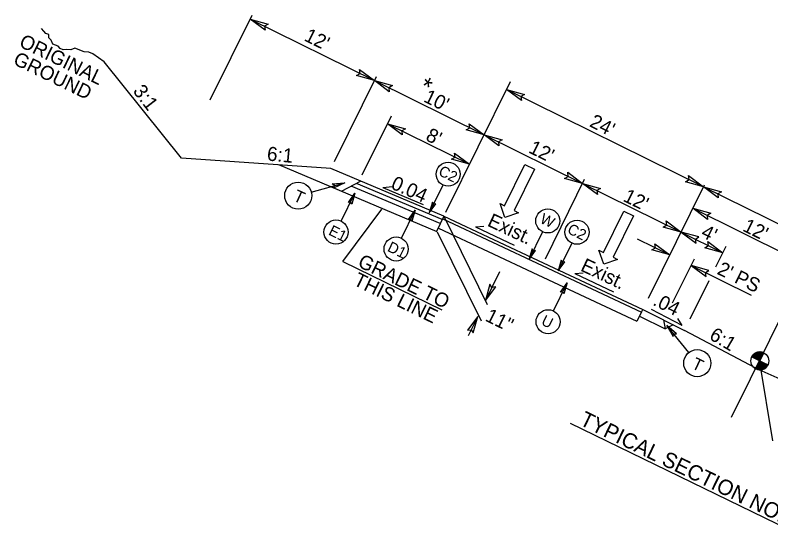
# Model space of a CAD drawing. Extents: x 1518247 to 1523638, y 635234 to 639927.
# Drawn here: x 1518468 to 1519070, y 637598 to 638013 of the extents above; entities that cross this region are included whole.
import ezdxf

# ---------------------------------------------------------------- set-up
doc = ezdxf.new("R2010")
doc.units = 0
for name, color, linetype in [('DTM TIN Hull White', 7, 'Continuous'), ('Prop Dimension', 7, 'Continuous'), ('Prop Dimension Text', 7, 'Continuous'), ('Prop Lane Arrow CELL', 7, 'Continuous'), ('Prop Shade Light', 7, 'Continuous'), ('Typical Grade Point Symbol CELL', 7, 'Continuous'), ('Typical Hinge Slope Interstate CELL', 7, 'Continuous'), ('Typical ID Circle CELL', 7, 'Continuous'), ('Typical Pavement Slope CELL', 7, 'Continuous'), ('Typical Pavement Slope Information CELL', 7, 'Continuous'), ('Typical Text Centerline CELL', 7, 'Continuous'), ('Typical Text General CELL', 7, 'Continuous'), ('Typical Text ID Circle CELL', 7, 'Continuous'), ('Typical Text Label CELL', 7, 'Continuous')]:
    doc.layers.add(name, color=color, linetype=linetype)

# ---------------------------------------------------------------- blocks, each defined once
blk = doc.blocks.new('TERMINATOR')
at = {"layer": 'Prop Shade Light'}
blk.add_lwpolyline([(-0.469, 0.081), (0, 0), (-0.471, -0.083), (-0.411, 0)], close=True, dxfattribs=at)

msp = doc.modelspace()

# ---------------------------------------------------------------- linework, layer by layer
at = {"layer": 'DTM TIN Hull White'}
for p, q in [((1518808.44, 637851.16), (1518887.66, 637813.98)), ((1518805, 637843.84), (1518884.23, 637806.66)), ((1518887.66, 637813.98), (1518966.8, 637776.83)), ((1518884.23, 637806.66), (1518963.07, 637769.66)), ((1518966.8, 637776.83), (1518963.07, 637769.66))]:
    msp.add_line(p, q, dxfattribs=at)
at = {"layer": 'Prop Dimension'}
for p, q in [((1518623.33, 637945.84), (1518656.73, 638013.45)), ((1518655.11, 638010.18), (1518754.1, 637961.28)), ((1518722.32, 637896.94), (1518755.71, 637964.55)), ((1518754.1, 637961.28), (1518841.47, 637918.12)), ((1518811.03, 637856.5), (1518862.46, 637960.62)), ((1519016.2, 637876.74), (1518859.31, 637954.24)), ((1518744.29, 637886.09), (1518767.58, 637933.23)), ((1518764.45, 637926.91), (1518829.78, 637894.64)), ((1518841.47, 637918.12), (1518919.91, 637879.37)), ((1518890.25, 637819.32), (1518921.53, 637882.64)), ((1518890.25, 637819.32), (1518921.53, 637882.64)), ((1518919.91, 637879.37), (1518998.36, 637840.62)), ((1518972.36, 637787.99), (1519016.9, 637878.16)), ((1519016.2, 637876.74), (1519107.11, 637831.83)), ((1518728.88, 637817.04), (1518760.04, 637858.8)), ((1519007.7, 637859.53), (1519098.61, 637814.63)), ((1518809.41, 637853.23), (1518844, 637782.95)), ((1518804.17, 637840.81), (1518839.01, 637770.02)), ((1518998.36, 637840.62), (1519031.62, 637824.19)), ((1518963.47, 637835.2), (1518989.36, 637822.41)), ((1519026.02, 637812.85), (1519034.23, 637829.47)), ((1518728.88, 637817.04), (1518807.71, 637778.68)), ((1518991.64, 637784.2), (1519008.94, 637819.22)), ((1519006.36, 637814.01), (1519054.28, 637790.34)), ((1518853.65, 637808.9), (1518842.51, 637785.99)), ((1519005.62, 637771.56), (1519020.67, 637802.03)), ((1518836.37, 637773.4), (1518828.87, 637757.98)), ((1519071.38, 637674.28), (1519061.24, 637736.88))]:
    msp.add_line(p, q, dxfattribs=at)
at = {"layer": 'Prop Lane Arrow CELL'}
for p, q in [((1518857.67, 637861.55), (1518873.95, 637894.51)), ((1518873.95, 637894.51), (1518881.72, 637890.67)), ((1518881.72, 637890.67), (1518865.44, 637857.71)), ((1518858.01, 637852.16), (1518854.14, 637863.3)), ((1518854.14, 637863.3), (1518857.67, 637861.55)), ((1518868.97, 637855.97), (1518858.01, 637852.16)), ((1518865.44, 637857.71), (1518868.97, 637855.97)), ((1518936.5, 637824.43), (1518952.78, 637857.39)), ((1518952.78, 637857.39), (1518960.55, 637853.55)), ((1518960.55, 637853.55), (1518944.27, 637820.6)), ((1518936.84, 637815.04), (1518932.97, 637826.18)), ((1518932.97, 637826.18), (1518936.5, 637824.43)), ((1518944.27, 637820.6), (1518947.8, 637818.85)), ((1518947.8, 637818.85), (1518936.84, 637815.04))]:
    msp.add_line(p, q, dxfattribs=at)
at = {"layer": 'Prop Shade Light'}
for points in [[(1518720.52, 637878.94), (1518730.6, 637879.94), (1518721.4, 637875.56), (1518722.15, 637877.61)], [(1518733.29, 637864.21), (1518738.57, 637871.51), (1518736.06, 637862.8), (1518735.14, 637864.51)], [(1518800.24, 637864.48), (1518797.72, 637855.83), (1518803.05, 637863.16), (1518801.14, 637862.84)], [(1518781.18, 637850.68), (1518786.46, 637857.97), (1518783.95, 637849.26), (1518783.03, 637850.98)], [(1518879.62, 637827.25), (1518877.1, 637818.61), (1518882.43, 637825.93), (1518880.52, 637825.61)], [(1518902.92, 637818.27), (1518900.39, 637809.62), (1518905.73, 637816.95), (1518903.81, 637816.63)], [(1518902.29, 637792.76), (1518907.57, 637800.06), (1518905.06, 637791.35), (1518904.14, 637793.06)], [(1518994.65, 637759.6), (1518987.06, 637766.31), (1518991.96, 637757.37), (1518992.55, 637759.47)]]:
    msp.add_lwpolyline(points, close=True, dxfattribs=at)
at = {"layer": 'Typical Grade Point Symbol CELL'}
for p, q in [((1519064.23, 637744.34), (1519061.08, 637737.93)), ((1519054.68, 637741.09), (1519061.08, 637737.93)), ((1519061.08, 637737.93), (1519054.68, 637741.09)), ((1519057.94, 637731.52), (1519061.08, 637737.93)), ((1519061.08, 637737.93), (1519067.5, 637734.79))]:
    msp.add_line(p, q, dxfattribs=at)
for points in [[(1519061.26, 637738.29), (1519054.86, 637741.42)], [(1519061.32, 637738.41), (1519054.92, 637741.55)], [(1519061.38, 637738.54), (1519055, 637741.67)], [(1519061.45, 637738.67), (1519055.08, 637741.79)], [(1519061.51, 637738.8), (1519055.16, 637741.91)], [(1519061.57, 637738.93), (1519055.25, 637742.03)], [(1519061.64, 637739.06), (1519055.33, 637742.15)], [(1519061.7, 637739.18), (1519055.42, 637742.26)], [(1519061.76, 637739.31), (1519055.51, 637742.38)], [(1519061.82, 637739.44), (1519055.6, 637742.49)], [(1519061.89, 637739.57), (1519055.69, 637742.6)], [(1519061.95, 637739.7), (1519055.8, 637742.71)], [(1519062.01, 637739.82), (1519055.89, 637742.83)], [(1519062.08, 637739.95), (1519055.99, 637742.93)], [(1519062.14, 637740.08), (1519056.1, 637743.04)], [(1519062.2, 637740.21), (1519056.2, 637743.15)], [(1519062.26, 637740.34), (1519056.32, 637743.25)], [(1519062.33, 637740.47), (1519056.44, 637743.35)], [(1519062.39, 637740.59), (1519056.56, 637743.45)], [(1519062.45, 637740.72), (1519056.68, 637743.55)], [(1519062.52, 637740.85), (1519056.8, 637743.65)], [(1519062.58, 637740.98), (1519056.94, 637743.74)], [(1519062.64, 637741.11), (1519057.07, 637743.84)], [(1519062.7, 637741.23), (1519057.21, 637743.93)], [(1519062.77, 637741.36), (1519057.35, 637744.02)], [(1519062.83, 637741.49), (1519057.5, 637744.1)], [(1519062.89, 637741.62), (1519057.65, 637744.19)], [(1519062.95, 637741.75), (1519057.8, 637744.27)], [(1519063.02, 637741.88), (1519057.96, 637744.35)], [(1519063.08, 637742), (1519058.12, 637744.43)], [(1519063.14, 637742.13), (1519058.3, 637744.51)], [(1519063.21, 637742.26), (1519058.48, 637744.58)], [(1519063.27, 637742.39), (1519058.65, 637744.65)], [(1519063.33, 637742.52), (1519058.84, 637744.72)], [(1519063.39, 637742.65), (1519059.05, 637744.77)], [(1519063.46, 637742.77), (1519059.26, 637744.83)], [(1519063.52, 637742.9), (1519059.47, 637744.88)], [(1519063.58, 637743.03), (1519059.69, 637744.93)], [(1519063.65, 637743.16), (1519059.93, 637744.98)], [(1519063.71, 637743.29), (1519060.18, 637745.02)], [(1519063.77, 637743.41), (1519060.44, 637745.05)], [(1519063.83, 637743.54), (1519060.73, 637745.06)], [(1519063.9, 637743.67), (1519061.03, 637745.07)], [(1519063.96, 637743.8), (1519061.37, 637745.07)], [(1519064.02, 637743.93), (1519061.73, 637745.05)], [(1519064.09, 637744.06), (1519062.18, 637744.99)], [(1519064.15, 637744.18), (1519062.7, 637744.9)], [(1519064.21, 637744.31), (1519063.51, 637744.65)], [(1519061.13, 637738.03), (1519054.72, 637741.17), (1519054.72, 637741.17)], [(1519061.2, 637738.16), (1519054.79, 637741.3)], [(1519065.76, 637732.55), (1519059.86, 637735.44)], [(1519065.88, 637732.65), (1519059.93, 637735.56)], [(1519066, 637732.75), (1519059.99, 637735.69)], [(1519066.11, 637732.85), (1519060.05, 637735.82)], [(1519066.21, 637732.96), (1519060.11, 637735.95)], [(1519066.32, 637733.07), (1519060.18, 637736.08)], [(1519066.41, 637733.18), (1519060.24, 637736.21)], [(1519066.51, 637733.29), (1519060.3, 637736.33)], [(1519066.61, 637733.4), (1519060.37, 637736.46)], [(1519066.7, 637733.52), (1519060.43, 637736.59)], [(1519066.79, 637733.63), (1519060.49, 637736.72)], [(1519066.88, 637733.75), (1519060.55, 637736.85)], [(1519066.96, 637733.87), (1519060.62, 637736.98)], [(1519067.03, 637733.99), (1519060.68, 637737.1)], [(1519067.11, 637734.11), (1519060.74, 637737.23)], [(1519067.19, 637734.23), (1519060.81, 637737.36)], [(1519067.26, 637734.35), (1519060.87, 637737.49)], [(1519067.33, 637734.48), (1519060.93, 637737.62)], [(1519067.4, 637734.6), (1519060.99, 637737.74)], [(1519067.47, 637734.73), (1519067.47, 637734.73), (1519061.06, 637737.87)], [(1519058.89, 637731.14), (1519057.98, 637731.59)], [(1519059.61, 637730.95), (1519058.04, 637731.72)], [(1519060.11, 637730.86), (1519058.1, 637731.85)], [(1519060.53, 637730.82), (1519058.17, 637731.97)], [(1519060.89, 637730.8), (1519058.23, 637732.1)], [(1519061.23, 637730.79), (1519058.29, 637732.23)], [(1519061.52, 637730.81), (1519058.36, 637732.36)], [(1519061.79, 637730.83), (1519058.42, 637732.49)], [(1519062.06, 637730.86), (1519058.48, 637732.62)], [(1519062.3, 637730.9), (1519058.54, 637732.74)], [(1519062.54, 637730.95), (1519058.61, 637732.87)], [(1519062.76, 637731), (1519058.67, 637733)], [(1519062.98, 637731.05), (1519058.73, 637733.13)], [(1519063.18, 637731.11), (1519058.79, 637733.26)], [(1519063.37, 637731.17), (1519058.86, 637733.39)], [(1519063.57, 637731.24), (1519058.92, 637733.51)], [(1519063.74, 637731.31), (1519058.98, 637733.64)], [(1519063.92, 637731.38), (1519059.05, 637733.77)], [(1519064.09, 637731.45), (1519059.11, 637733.9)], [(1519064.26, 637731.53), (1519059.17, 637734.03)], [(1519064.41, 637731.62), (1519059.23, 637734.15)], [(1519064.57, 637731.7), (1519059.3, 637734.28)], [(1519064.72, 637731.79), (1519059.36, 637734.41)], [(1519064.87, 637731.87), (1519059.42, 637734.54)], [(1519065, 637731.97), (1519059.49, 637734.67)], [(1519065.13, 637732.06), (1519059.55, 637734.8)], [(1519065.27, 637732.15), (1519059.61, 637734.92)], [(1519065.4, 637732.25), (1519059.67, 637735.05)], [(1519065.52, 637732.35), (1519059.74, 637735.18)], [(1519065.64, 637732.45), (1519059.8, 637735.31)]]:
    msp.add_lwpolyline(points, dxfattribs=at)
msp.add_circle((1519061.09, 637737.94), 7.14, dxfattribs=at)
for start, end in [(63.88665, 153.88665), (243.88665, 333.88665)]:
    msp.add_arc((1519061.09, 637737.94), 7.14, start, end, dxfattribs=at)
at = {"layer": 'Typical Hinge Slope Interstate CELL'}
for p, q in [((1518600.43, 637899.48), (1518538.83, 637976.26)), ((1518719.46, 637891.15), (1518600.43, 637899.48)), ((1518804.17, 637840.81), (1518677.83, 637894.06)), ((1518809.41, 637853.23), (1518719.46, 637891.15)), ((1518743.23, 637881.13), (1518727.47, 637872.87)), ((1518806.38, 637847.31), (1518735.62, 637877.14)), ((1518807.96, 637850.55), (1518739.75, 637879.31)), ((1518809.41, 637853.23), (1518803.49, 637841.09)), ((1518809.41, 637853.23), (1518888.63, 637816.05)), ((1518888.63, 637816.05), (1518967.85, 637778.87)), ((1518966.8, 637776.83), (1518967.82, 637778.89)), ((1518967.85, 637778.87), (1519001.04, 637762.29)), ((1518965.16, 637773.68), (1518985.62, 637763.45)), ((1518984.32, 637770.64), (1518985.62, 637763.45)), ((1518992.01, 637766.8), (1518985.62, 637763.45)), ((1519057.86, 637732.14), (1519001.04, 637762.29)), ((1519057.86, 637732.13), (1519117.27, 637705.63))]:
    msp.add_line(p, q, dxfattribs=at)
msp.add_lwpolyline([(1518538.83, 637976.26), (1518529.76, 637982.62), (1518526.52, 637983.92), (1518522.86, 637984.14), (1518520.7, 637985), (1518517.45, 637986.3), (1518515.3, 637987.17), (1518512.27, 637985.87), (1518508.59, 637986.09), (1518506, 637985.88), (1518503.84, 637986.74), (1518502.12, 637988.69), (1518499.96, 637989.56), (1518497.8, 637990.42), (1518496.51, 637993.45), (1518494.78, 637995.4), (1518494.57, 637997.99), (1518492.41, 637998.85), (1518490.68, 638000.79), (1518488.95, 638002.74), (1518488.86, 638002.85)], dxfattribs=at)
at = {"layer": 'Typical ID Circle CELL'}
for p, q in [((1518703.74, 637872.53), (1518730.6, 637879.94)), ((1518808.59, 637878.1), (1518797.72, 637855.83)), ((1518727.67, 637849.26), (1518738.57, 637871.51)), ((1518775.55, 637835.73), (1518786.46, 637857.97)), ((1518887.97, 637840.87), (1518877.1, 637818.61)), ((1518911.26, 637831.89), (1518900.39, 637809.62)), ((1518896.67, 637777.81), (1518907.57, 637800.06)), ((1519004.49, 637744.57), (1518987.06, 637766.31))]:
    msp.add_line(p, q, dxfattribs=at)
for centre, radius in [((1518812.79, 637886.71), 9.59), ((1518693.35, 637869.66), 10.78), ((1518892.17, 637849.48), 9.59), ((1518723.45, 637840.65), 9.59), ((1518915.47, 637840.5), 9.59), ((1518771.34, 637827.12), 9.59), ((1518892.45, 637769.2), 9.59), ((1519011.24, 637736.16), 10.78)]:
    msp.add_circle(centre, radius, dxfattribs=at)
at = {"layer": 'Typical Pavement Slope Information CELL'}
for p, q in [((1518760.74, 637876.04), (1518768.47, 637877.01)), ((1518760.74, 637876.04), (1518792.89, 637862.49)), ((1518834.62, 637844.75), (1518841.27, 637845.32)), ((1518834.62, 637844.75), (1518865.4, 637830.3)), ((1518913.84, 637807.57), (1518920.49, 637808.13)), ((1518913.84, 637807.57), (1518944.62, 637793.12)), ((1518999.29, 637766.25), (1518974.92, 637778.9)), ((1518999.29, 637766.25), (1518995.7, 637771.87))]:
    msp.add_line(p, q, dxfattribs=at)
at = {"layer": 'Typical Text Centerline CELL'}
msp.add_line((1519038.56, 637693.07), (1519104.64, 637826.83), dxfattribs=at)
at = {"layer": 'Typical Text Label CELL'}
msp.add_line((1518910.12, 637688.4), (1519096.33, 637597.78), dxfattribs=at)

# ---------------------------------------------------------------- block references
at = {"layer": 'Prop Dimension'}
for p, xscale, yscale, rotation in [((1518655.11, 638010.18), 30.9388560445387, 33.305184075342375, 153.71146049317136), ((1518754.1, 637961.28), 30.9388560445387, 33.305184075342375, -26.28853950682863), ((1518754.1, 637961.28), 30.9388560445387, 33.305184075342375, 153.71146049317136), ((1518859.31, 637954.24), 30.9388560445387, 33.305184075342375, 153.71146049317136), ((1518764.45, 637926.91), 30.9388560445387, 33.305184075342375, 153.71146049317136), ((1518841.47, 637918.12), 30.9388560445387, 33.305184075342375, -26.28853950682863), ((1518841.47, 637918.12), 30.9388560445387, 33.305184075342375, 153.71146049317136), ((1518829.78, 637894.64), 30.9388560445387, 33.305184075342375, -26.28853950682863), ((1518919.91, 637879.37), 30.9388560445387, 33.305184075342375, -26.28853950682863), ((1518919.91, 637879.37), 30.9388560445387, 33.305184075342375, 153.71146049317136), ((1519016.2, 637876.74), 30.9388560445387, 33.305184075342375, -26.28853950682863), ((1519016.2, 637876.74), 30.9388560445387, 33.305184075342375, 153.71146049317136), ((1519007.7, 637859.53), 30.9388560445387, 33.305184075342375, 153.71146049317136), ((1518998.36, 637840.62), 30.9388560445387, 33.305184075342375, -26.28853950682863), ((1518998.36, 637840.62), 30.938856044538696, -33.30518407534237, 154.1639887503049), ((1519031.62, 637824.19), 30.9388560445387, 33.305184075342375, -26.28853950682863), ((1518989.36, 637822.41), 30.9388560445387, 33.305184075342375, -26.28853950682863), ((1519006.36, 637814.01), 30.938856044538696, -33.30518407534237, 154.1639887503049), ((1518842.51, 637785.99), 28.531901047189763, -30.714135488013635, -115.94890411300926), ((1518836.37, 637773.4), 28.531901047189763, -30.714135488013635, 64.05109588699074)]:
    msp.add_blockref('TERMINATOR', p, dxfattribs=dict(at, xscale=xscale, yscale=yscale, rotation=rotation))

# ---------------------------------------------------------------- texts
for s, height, rotation, p in [("12'", 11.189, 333.71146, (1518697.29, 637993.55)), ('*', 14.55, 334.16399, (1518788.71, 637951.8)), ("10'", 11.189, 334.16399, (1518792.47, 637944.83)), (" 24' ", 11.189, 333.71146, (1518920.92, 637926.94)), ("8'", 11.189, 333.71146, (1518794.15, 637914.14)), ("12'", 11.189, 333.71146, (1518876.18, 637904.28)), ("12'", 11.189, 333.71146, (1518951.43, 637865.7)), ("12'", 11.189, 333.71146, (1519046.68, 637841.96)), ("4'", 11.189, 333.71146, (1519013.49, 637837.19)), ("2' PS", 11.189, 333.71146, (1519026.31, 637807.59)), ('.04', 11.189, 333.71146, (1518975.15, 637782.75)), ('11"', 11.189, 333.71146, (1518841.54, 637770.33)), ('6:1', 11.189, 329.53488, (1519020.05, 637755.8))]:
    msp.add_text(s, height=height, rotation=rotation, dxfattribs=at).set_placement(p)
at = {"layer": 'Prop Dimension Text'}
msp.add_text('TYPICAL SECTION NO. 5', height=12.2298, rotation=334.0511, dxfattribs=at).set_placement((1518916.71, 637687.4))
at = {"layer": 'Typical Hinge Slope Interstate CELL'}
for s, p in [('ORIGINAL', (1518470.22, 637988.81)), ('GROUND', (1518465.48, 637974.77))]:
    msp.add_text(s, height=11.211, rotation=334.0511, dxfattribs=at).set_placement(p)
at = {"layer": 'Typical Pavement Slope CELL'}
for s, rotation, p in [('3:1', 307.70556, (1518561.15, 637952.78)), ('6:1', 354.63192, (1518668.12, 637897.65)), ('0.04 ', 336.00289, (1518766.47, 637875.56))]:
    msp.add_text(s, height=11.189, rotation=rotation, dxfattribs=at).set_placement(p)
at = {"layer": 'Typical Pavement Slope Information CELL'}
for p in [(1518843.32, 637845.88), (1518917.53, 637810.15)]:
    msp.add_text('Exist.', height=11.189, rotation=334.8572, dxfattribs=at).set_placement(p)
at = {"layer": 'Typical Text General CELL'}
for s, p in [('GRADE TO', (1518740, 637813.51)), ('THIS LINE', (1518736.51, 637798.87))]:
    msp.add_text(s, height=11.211, rotation=334.0511, dxfattribs=at).set_placement(p)
at = {"layer": 'Typical Text ID Circle CELL'}
for s, height, rotation, p in [('C2', 8.581, 333.97927, (1518804.36, 637886.32)), ('T', 9.65, 335.46996, (1518688.63, 637865.98)), ('W', 8.58, 333.97927, (1518885.26, 637848.35)), ('E1', 8.581, 333.89618, (1518716.85, 637838.84)), ('C2', 8.581, 333.97927, (1518907.04, 637840.11)), ('D1', 8.581, 333.89618, (1518763.69, 637825.82)), ('U', 8.58, 333.89618, (1518886.3, 637767.17)), ('T', 9.65, 334.25656, (1519006.06, 637732.44))]:
    msp.add_text(s, height=height, rotation=rotation, dxfattribs=at).set_placement(p)

doc.saveas('drawing.dxf')
